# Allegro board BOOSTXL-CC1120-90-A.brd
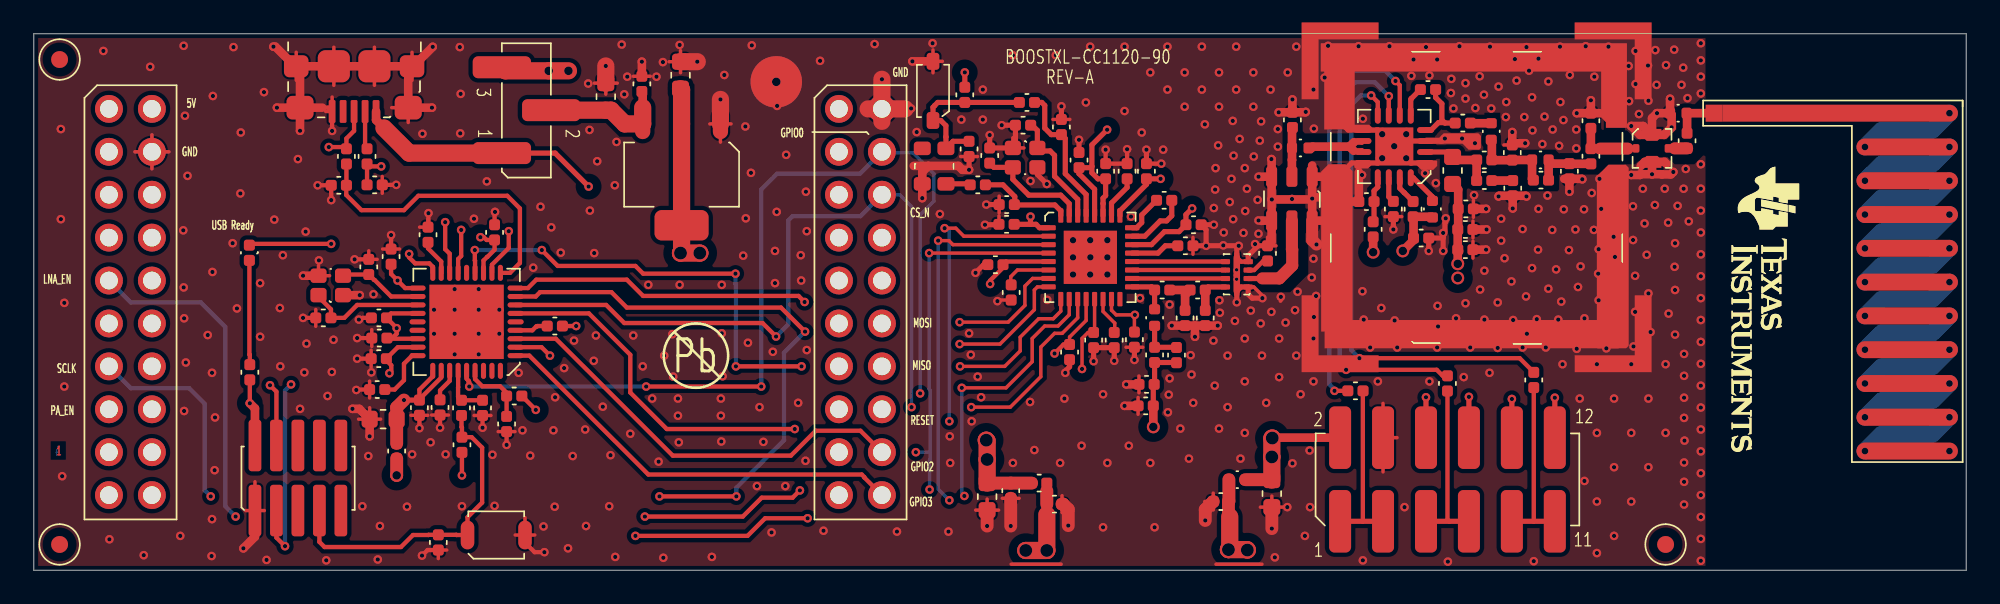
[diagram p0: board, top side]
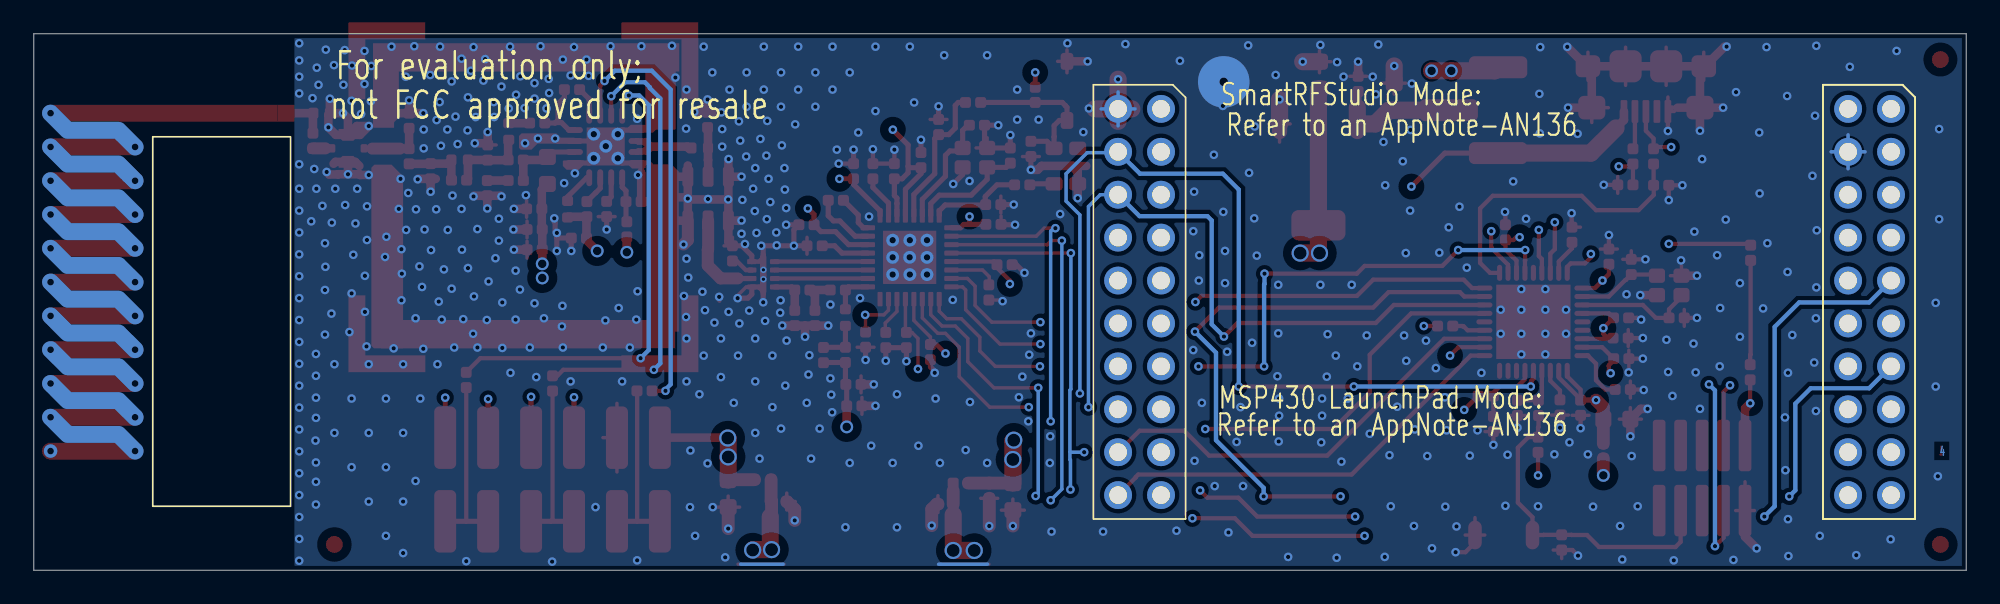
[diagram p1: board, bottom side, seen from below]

Outline 114.3 x 31.75 mm; copper layers: TOP, LAYER2, LAYER3, BOTTOM. Coordinates in mm from the lower left corner of the outline.
Outline path: 0,31.75 114.3,31.75 114.3,0 0,0 0,31.75

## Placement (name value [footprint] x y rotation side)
A1  Antenna PCB 868/915MHz  [ANTENNA868_915MHZ_A2N]  99.39 27.05 270 top
C1  100nF  [CAPC1005X60N]  59.92 3.91 0 top
C2  DNP  [CAPC1005X60N]  57.78 5.16 270 top
C3  2.2uF  [CAPC1608X90N]  56.39 5.16 270 top
C4  47nF  [CAPC1005X60N]  61.26 13.36 270 top
C5  47nF  [CAPC1005X60N]  57.33 18.08 180 top
C6  220nF  [CAPC1005X60N]  57.81 16.89 270 top
C7  47nF  [CAPC1005X60N]  57.99 20.47 180 top
C8  47nF  [CAPC1005X60N]  62.69 14.07 270 top
C9  47nF  [CAPC1005X60N]  65.1 14.1 270 top
C10  33pF  [CAPC1005X60N]  67.59 13.18 270 top
C11  10nF  [CAPC1005X60N]  66.22 9.73 180 top
C12  100pF  [CAPC1005X60N]  66.27 11 180 top
C13  15pF  [CAPC1005X60N]  66.29 16.59 0 top
C14  10nF  [CAPC1005X60N]  67.67 19.2 0 top
C15  47nF  [CAPC1005X60N]  65.81 23.16 90 top
C16  1.8nF  [CAPC1005X60N]  67.31 21.89 180 top
C17  47nF  [CAPC1005X60N]  61.82 23.83 90 top
C18  47nF  [CAPC1005X60N]  68.15 20.45 0 top
C19  47nF  [CAPC1005X60N]  63.4 23.16 90 top
C20  47nF  [CAPC1005X60N]  64.67 23.16 90 top
C21  47nF  [CAPC1005X60N]  60.78 25.78 90 top
C22  0  [CAPC1005X60N]  58.06 26.34 0 top
C23  DNP  [CAPC1005X60N]  56.54 24.99 270 top
C24  22pF  [CAPC1005X60N]  56.29 22.81 180 top
C25  100nF  [CAPC1005X60N]  55.32 24.49 90 top
C26  0.8pF  [CAPC1005X60N]  74.45 27.1 270 top
C27  220pF  [CAPC1005X60N]  70.66 4.06 180 top
C28  10uF  [CAPC1608X100N]  73.23 5.33 270 top
C29  15pF  [CAPC1005X60N]  79.27 21.82 180 top
C30  27pF  [CAPC1005X60N]  81.61 19.66 0 top
C31  47pF  [CAPC1005X60N]  84.25 21.39 0 top
C32  1nF  [CAPC1005X60N]  84.23 20.17 0 top
C33  1uF  [CAPC1005X60N]  84.23 18.97 0 top
C34  12pF  [CAPC1005X60N]  82.02 28.45 0 top
C35  47pF  [CAPC1005X60N]  85.34 24.28 0 top
C36  12pF  [CAPC1005X60N]  84.07 26.47 0 top
C37  3.3pF  [CAPC1005X60N]  87.45 25.17 270 top
C38  7.5pF  [CAPC1005X60N]  90.83 23.16 90 top
C39  DNP  [CAPC1005X60N]  92.1 27.05 270 top
C40  1pF  [CAPC1005X60N]  97.79 24.97 90 top
C41  100nF  [CAPC1005X60N]  27.25 20.45 270 top
C42  2.2uF  [CAPC1608X90N]  21.46 8.94 180 top
C43  220pF  [CAPC1005X60N]  21.13 18.11 90 top
C44  1uF  [CAPC1005X60N]  24.03 10.08 270 top
C45  100nF  [CAPC1005X60N]  19.96 14.94 0 top
C46  100nF  [CAPC1005X60N]  19.99 13.74 0 top
C47  220pF  [CAPC1005X60N]  20.85 12.52 180 top
C48  100nF  [CAPC1005X60N]  22.81 9.17 90 top
C49  47pF  [CAPC1005X60N]  18.49 22.78 180 top
C50  47pF  [CAPC1005X60N]  19.71 22.81 0 top
C51  1nF  [CAPC1005X60N]  26.54 10.06 270 top
C52  33pF  [CAPC1005X60N]  17.58 14.94 180 top
C53  33pF  [CAPC1005X60N]  19.81 17.5 90 top
C56  100nF  [CAPC1005X60N]  35.97 29.24 270 top
C57  10uF  [CAPC1608X100N]  33.83 27.23 90 top
C58  10uF  [CAPC1608X100N]  38.25 28.5 90 top
C59  DNP  [CAPC1005X60N]  87.48 23.06 270 top
C60  DNP  [CAPC1005X60N]  88.7 23.09 0 top
CR1  SML-LX0402SUGC  [LEDC1005X70N]  12.75 18.34 90 top
CR2  1.8V  [SOD3716X135AN]  53.19 26.62 90 top
FIDU1  FIDU_1MM  [FID100X115]  96.52 1.52 0 top
FIDU2  FIDU_1MM  [FID100X115]  1.52 1.52 0 top
FIDU3  FIDU_1MM  [FID100X115]  1.52 30.23 0 top
FL1  LFD21868MMF1D386  [FIL_LFD21868MMF1D386N]  71.83 16.76 90 top
FL2  B39921B3588U410  [FIL_DCC6CN]  75.62 23.29 180 top
J3  1551372-1  [TE_1551372-1_A2N]  94.77 24.97 270 top
J4  1981568-1  [TYCO_19815681N]  20.24 27.15 90 top
L1  BLM15HG102SN1  [INDC1005X60N]  59.92 5.16 180 top
L2  8.2nH  [IND_LQW15AN]  66.29 15.44 270 top
L3  10nH  [IND_LQW15AN]  74.42 24.99 0 top
L4  10nH  [IND_LQW15AN]  70.69 5.36 0 top
L5  1.5nH  [INDC1005X60N]  79.22 20.62 270 top
L6  15nH  [IND_LQW15AN]  82.73 20.88 90 top
L7  22nH  [INDC1608X100N]  83.92 22.86 90 top
L8  7.5nH  [IND_LQW15AN]  86.21 25.48 90 top
L9  2.9nH  [IND_LQW15AN]  88.62 24.28 0 top
L10  9.1nH  [INDC1005X60N]  92.1 24.05 90 top
L11  12nH  [IND_LQW15AN]  97.76 27.05 180 top
L12  BLM15HG102SN1  [INDC1005X60N]  21.46 6.6 90 top
L13  DNP  [INDC1005X60N]  85.34 23.06 0 top
NOREF  -  [#2]  0 0 90 top
NOREF#2  -  [#2]  32.72 0.81 0 top
NOREF#3  -  [#2]  12.29 23.98 0 top
NOREF#4  -  [#2]  -8.36 -41.35 0 top
NOREF#5  -  [#2]  39.17 12.7 0 top
NOREF#6  -  [#2]  0 0 0 top
P1  FTSH-105-01-L-DV-K  [SAMTEC_FTSH-105-01-L-DV-K-10CN]  13.08 3.53 0 top
P2  SSW-110-23-F-D  [SAMTEC_TSW11008SDB]  4.45 27.3 270 top
P3  SSW-110-23-F-D  [SAMTEC_TSW11008SDB]  47.62 27.3 270 top
P6  TSM-106-01-L-DV-P  [SAMTEC_TSM10601LDVPN]  77.27 2.9 0 top
P7  TSM-103-01-L-SV-P  [SAMTEC_TSM10301LSVPN]  27.69 24.69 0 top
R1  56k  [RESC1005X40N]  63.91 14.07 270 top
R3  10  [RESC1005X40N]  66.29 12.29 90 top
R4  DNP  [RESC1005X40N]  57.1 21.64 0 top
R5  470  [RESC1005X40N]  55.07 27.69 90 top
R7  0  [RESC1005X40N]  69.29 16.59 180 top
R8  DNP  [RESC1005X40N]  68.1 14.48 90 top
R9  DNP  [RESC1005X40N]  69.29 14.48 90 top
R10  DNP  [RESC1005X40N]  72.97 19.2 270 top
R11  3.3k  [RESC1005X40N]  80.42 20.93 90 top
R12  47  [RESC1005X40N]  81.58 21.82 270 top
R14  33  [RESC1005X40N]  18.49 24.94 270 top
R15  33  [RESC1005X40N]  19.71 24.94 270 top
R16  1.5k  [RESC1005X40N]  31.27 14.45 180 top
R17  2.7k  [RESC1005X40N]  25.3 10.06 270 top
R18  56k  [RESC1005X40N]  19.86 10.69 0 top
R19  1k  [RESC1005X40N]  12.78 12.17 270 top
R20  1k  [RESC1005X40N]  23.32 19.41 90 top
R21  10k  [RESC1005X40N]  27.97 10.31 0 top
R22  18k  [RESC1005X40N]  27.97 8.2 90 top
R23  10k  [RESC1005X40N]  77.72 10.62 0 top
R24  10k  [RESC1005X40N]  83.62 11.51 270 top
R25  10k  [RESC1005X40N]  88.72 11.71 270 top
R26  4.7k  [RESC1005X40N]  25.32 7.87 270 top
R27  DNP  [RESC1005X40N]  23.93 1.19 90 top
R28  DNP  [RESC1005X40N]  58.29 27.69 0 top
SC1  BMIS-202-F  [MECH_BMIS202FN]  77.27 14 0 top
SW1  B3U-1000PM  [SW_B3U-1000PN]  25.65 2.08 0 top
U1  CC112x/CC120xRHB  [QFNFC50P500X500X100-33BN]  60.02 20.27 270 top
U2  CC1190  [QFNFC65P400X400X100-17AN]  82.32 24.1 90 top
U3  TG-5006CG  [OSCCC200X250X90-4BN]  52.55 24.97 270 top
U4  CC2511F16  [QFNWB50P600X600X90-37N]  28.5 12.7 90 top
U5  TLV1117LV33DCY  [SOT230P700X180-4AN]  40.61 26.42 180 top
UNK#REFDES  -  [unnamed]  104.42 22.89 270 top
Y1  DNP  [XTAL_FA128N]  59.36 24.99 180 top
Y2  48MHz  [XTAL_FA128N]  16.84 16.28 0 top

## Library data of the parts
A1 = ANTENNA: User Part Number: #PN
C1 C2 C4-C9 C11-C27 C29-C41 C43-C51 C56 C59 C60 = CAPACITOR: User Part Number: #PN; alternate symbols: (CAPC1005X60L,CAPC1005X60M)
C3 C42 = CAPACITOR: alternate symbols: (CAPC1608X90L,CAPC1608X90M)
C10 C52 C53 = CAPACITOR: User Part Number: #PN; alternate symbols: (CAPC1005X60M,CAPC1005X60L)
C28 C57 C58 = CAPACITOR: alternate symbols: (CAPC1608X100L,CAPC1608X100M)
CR1 = LED_AC: alternate symbols: (LEDC1005X70L,LEDC1005X70M)
CR2 = DIODE_ZENER: alternate symbols: (SOD3716X135AL,SOD3716X135AM)
FIDU1-FIDU3 = FIDMARK
FL1 = FILTER_LFD21868MMF1D386: alternate symbols: (FIL_LFD21868MMF1D386L,FIL_LFD21868MMF1D386M)
FL2 = FILTER_SAW_RF_B3588: alternate symbols: (FIL_DCC6CL,FIL_DCC6CM)
J3 = CONN_COAX_1551372-1: User Part Number: #PN; alternate symbols: (TE_1551372-1_A2L,TE_1551372-1_A2M)
J4 = CONN_USB_MICRO_5+6_S: alternate symbols: (TYCO_19815681L,TYCO_19815681M)
L1 L5 L10 L12 L13 = INDUCTOR: alternate symbols: (INDC1005X60L,INDC1005X60M)
L2-L4 L6 L8 L9 L11 = INDUCTOR: alternate symbols: (IND_LQW15AM,IND_LQW15AL)
L7 = INDUCTOR: alternate symbols: (INDC1608X100L,INDC1608X100M)
P1 = CONN_HEADER_2X5: alternate symbols: (SAMTEC_FTSH-105-01-L-DV-K-10CL,SAMTEC_FTSH-105-01-L-DV-K-10CM)
P2 P3 = CONN_HEADER_2X10_P_S_V1: alternate symbols: (SAMTEC_TSW11008SDC,SAMTEC_TSW11008SDA)
P6 = CONN_HEADER_2X6_P_S: User Part Number: #PN; alternate symbols: (SAMTEC_TSM10601LDVPL,SAMTEC_TSM10601LDVPM)
P7 = CONN_HEADER_3_P_S: User Part Number: #PN; alternate symbols: (SAMTEC_TSM10301LSVPL,SAMTEC_TSM10301LSVPM)
R1 R3-R5 R7-R12 R14-R28 = RESISTOR: alternate symbols: (RESC1005X40L,RESC1005X40M)
SC1 = SHIELD_COVER_BMIS-202: User Part Number: #PN
SW1 = SWITCH_2PIN: alternate symbols: (SW_B3U-1000PL,SW_B3U-1000PM)
U1 = IC_RF_CC1120_QFN32: alternate symbols: (QFNFC50P500X500X100-33BL,QFNFC50P500X500X100-33BM)
U2 = IC_RF_CC1190_QFN16: alternate symbols: (QFNFC65P400X400X100-17AL,QFNFC65P400X400X100-17AM)
U3 = XTAL_TG-5021CG: alternate symbols: (OSCCC200X250X90-4BL,OSCCC200X250X90-4BM)
U4 = IC_RF_CC2511F_QFN36: alternate symbols: (QFNWB50P600X600X90-37L,QFNWB50P600X600X90-37M)
U5 = IC_PM_LM317M_SOT223-4: alternate symbols: (SOT230P700X180-4AL,SOT230P700X180-4AM)
Y1 Y2 = XTAL_4: alternate symbols: (XTAL_FA128L,XTAL_FA128M)

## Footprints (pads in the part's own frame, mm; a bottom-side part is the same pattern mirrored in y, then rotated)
ANTENNA868_915MHZ_A2N
  rect 1x1 smd: 1(0,0)
CAPC1005X60N
  custom 0.16x0.16 smd: 1(0,0) 2(0.9,0)
CAPC1608X90N
  custom 0.237x0.237 smd: 1(0,0) 2(1.6,0)
CAPC1608X100N
  custom 0.237x0.237 smd: 1(0,0) 2(1.6,0)
FID100X115
  round 1 smd: 1(0,0)
FIL_DCC6CN
  custom 0.163x0.163 smd: 1(0,0) 2(1.2,0) 3(2.4,0) 4(2.4,2.6) 5(1.2,2.6) 6(0,2.6)
FIL_LFD21868MMF1D386N
  custom 0.075x0.075 smd: 1(0,0) 2(0.5,0) 3(1,0) 4(1.5,0) 5(1.75,0.675) 6(1.5,1.35) 7(1,1.35) 8(0.5,1.35) 9(0,1.35) 10(-0.25,0.675)
IND_LQW15AN
  custom 0.15x0.15 smd: 1(0,0) 2(0.98,0)
INDC1005X60N
  custom 0.16x0.16 smd: 1(0,0) 2(0.9,0)
INDC1608X100N
  custom 0.237x0.237 smd: 1(0,0) 2(1.6,0)
LEDC1005X70N
  custom 0.163x0.163 smd: 1(0,0) 2(0.9,0)
MECH_BMIS202FN
  custom 1.138x1.138 smd: 1(0,0) 3(16.15,0) 5(16.15,16.15) 7(0,16.15)
  custom 0.25x0.25 smd: 2(8.075,-0.075) 4(16.225,8.075) 6(8.075,16.225) 8(-0.075,8.075)
OSCCC200X250X90-4BN
  custom 0.199x0.199 smd: 1(0,0) 2(2.1,0) 3(2.1,1.4) 4(0,1.4)
QFNFC50P500X500X100-33BN
  custom 0.075x0.075 smd: 1(0,0) 2(0.5,0) 3(1,0) 4(1.5,0) 5(2,0) 6(2.5,0) 7(3,0) 8(3.5,0) 9(4.225,0.725) 10(4.225,1.225) 11(4.225,1.725) 12(4.225,2.225) 13(4.225,2.725) 14(4.225,3.225) 15(4.225,3.725) 16(4.225,4.225) 17(3.5,4.95) 18(3,4.95) 19(2.5,4.95) 20(2,4.95) 21(1.5,4.95) 22(1,4.95) 23(0.5,4.95) 24(0,4.95) 25(-0.725,4.225) 26(-0.725,3.725) 27(-0.725,3.225) 28(-0.725,2.725) 29(-0.725,2.225) 30(-0.725,1.725) 31(-0.725,1.225) 32(-0.725,0.725)
  rect 3.15x3.15 smd: 33(1.75,2.475)
QFNFC65P400X400X100-17AN
  oval 0.35x1 smd: 1(0,0) 2(0.65,0) 3(1.3,0) 4(1.95,0) 9(1.95,3.7) 10(1.3,3.7) 11(0.65,3.7) 12(0,3.7)
  oval 1x0.35 smd: 5(2.825,0.875) 6(2.825,1.525) 7(2.825,2.175) 8(2.825,2.825) 13(-0.875,2.825) 14(-0.875,2.175) 15(-0.875,1.525) 16(-0.875,0.875)
  rect 2.25x2.25 smd: 17(0.975,1.85)
QFNWB50P600X600X90-37N
  oval 0.3x0.95 smd: 1(0,0) 2(0.5,0) 3(1,0) 4(1.5,0) 5(2,0) 6(2.5,0) 7(3,0) 8(3.5,0) 9(4,0) 19(4,5.8) 20(3.5,5.8) 21(3,5.8) 22(2.5,5.8) 23(2,5.8) 24(1.5,5.8) 25(1,5.8) 26(0.5,5.8) 27(0,5.8)
  oval 0.95x0.3 smd: 10(4.9,0.9) 11(4.9,1.4) 12(4.9,1.9) 13(4.9,2.4) 14(4.9,2.9) 15(4.9,3.4) 16(4.9,3.9) 17(4.9,4.4) 18(4.9,4.9) 28(-0.9,4.9) 29(-0.9,4.4) 30(-0.9,3.9) 31(-0.9,3.4) 32(-0.9,2.9) 33(-0.9,2.4) 34(-0.9,1.9) 35(-0.9,1.4) 36(-0.9,0.9)
  rect 4.4x4.4 smd: 37(2,2.9)
RESC1005X40N
  custom 0.16x0.16 smd: 1(0,0) 2(0.9,0)
SAMTEC_FTSH-105-01-L-DV-K-10CN
  custom 0.187x0.187 smd: 1(0,0) 2(0,3.85) 3(1.27,0) 4(1.27,3.85) 5(2.54,0) 6(2.54,3.85) 7(3.81,0) 8(3.81,3.85) 9(5.08,0) 10(5.08,3.85)
SAMTEC_TSM10301LSVPN
  custom 0.325x0.325 smd: 1(0,0) 2(2.92,2.54) 3(0,5.08)
SAMTEC_TSM10601LDVPN
  custom 0.325x0.325 smd: 1(0,0) 2(0,4.95) 3(2.54,0) 4(2.54,4.95) 5(5.08,0) 6(5.08,4.95) 7(7.62,0) 8(7.62,4.95) 9(10.16,0) 10(10.16,4.95) 11(12.7,0) 12(12.7,4.95)
SAMTEC_TSW11008SDB
  round 1.65 hole 1.05: 1(0,0) 2(0,2.54) 3(2.54,0) 4(2.54,2.54) 5(5.08,0) 6(5.08,2.54) 7(7.62,0) 8(7.62,2.54) 9(10.16,0) 10(10.16,2.54) 11(12.7,0) 12(12.7,2.54) 13(15.24,0) 14(15.24,2.54) 15(17.78,0) 16(17.78,2.54) 17(20.32,0) 18(20.32,2.54) 19(22.86,0) 20(22.86,2.54)
SOD3716X135AN
  custom 0.187x0.187 smd: 1(0,0) 2(3.5,0)
SOT230P700X180-4AN
  oval 0.9x1.8 smd: 1(0,0) 2(2.3,0) 3(4.6,0)
  custom 0.45x0.45 smd: 4(2.3,6)
SW_B3U-1000PN
  oval 0.8x1.7 smd: 1(0,0) 2(3.4,0)
TE_1551372-1_A2N
  custom 0.1x0.1 smd: 1(0,0) 2(0,1.9)
  custom 0.175x0.175 smd: M1(-0.8,0.95) M2(0.8,0.95)
TYCO_19815681N
  custom 0.1x0.1 smd: 1(0,0) 2(0,0.65) 3(0,1.3) 4(0,1.95) 5(0,2.6)
  custom 0.35x0.35 smd: 6(0.225,-1.903) 7(0.225,4.497)
  custom 0.325x0.325 smd: 8(2.675,-2.128) 9(2.675,4.722)
  custom 0.475x0.475 smd: 10(2.675,0.097) 11(2.675,2.497)
unnamed
  round 0.001 smd: 1(1.65,-3.9)
XTAL_FA128N
  custom 0.212x0.212 smd: 1(0,0) 2(1.45,0) 3(1.45,1.15) 4(0,1.15)

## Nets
3V3: C1.1 C27.1 C58.1 L1.1 L4.1 L12.1 P1.2 R19.2 R26.2 U5.2(OUT#2) U5.4(OUT#4)
GND: C1.2 C2.2 C3.2 C4.2 C5.2 C6.2 C7.2 C8.2 C9.2 C11.2 C12.2 C14.2 C15.2 C17.2 C18.2 C19.2 C20.2 C21.2 C22.1 C23.1 C25.1 C26.1 C27.2 C28.2 C29.2 C30.2 C31.2 C32.2 C33.2 C37.1 C38.1 C39.1 C41.1 C42.2 C43.2 C44.2 C45.1 C46.1 C47.2 C48.1 C49.2 C50.2 C51.2 C52.2 C53.2 C56.1 C57.2 C58.2 C59.2 CR2.2(ANODE) FL1.1(GND#1) FL1.4(GND#4) FL1.5(GND#5) FL1.10(GND#10) FL2.1(GND#1) FL2.3(GND#3) FL2.4(GND#4) FL2.6(GND#6) J3.M1 J3.M2 J4.5(GND#5) J4.6(GND#6) J4.7(GND#7) J4.8(GND#8) J4.9(GND#9) J4.10(GND#10) J4.11(GND#11) L11.2 P1.1 P2.4 P3.2 P6.4 R1.2 R4.1 R8.1 R9.1 R10.1 R11.1 R18.1 R20.2 R22.1 R27.1 SC1.1(GND#1) SC1.2(GND#2) SC1.3(GND#3) SC1.4(GND#4) SC1.5(GND#5) SC1.6(GND#6) SC1.7(GND#7) SC1.8(GND#8) SW1.2 U1.33(EGP) U2.1(GND#1) U2.3(GND#3) U2.9(GND#9) U2.12(GND#12) U2.17(GND#17) U3.2(GND) U4.37(AGND) U5.1(ADJ) Y1.2 Y1.4 Y2.2 Y2.4
VDD_CC112X: C2.1 C3.1 C4.1 C5.1 C7.1 C8.1 C9.1 C10.2 C11.1 C12.1 C15.1 C17.1 C18.1 C19.1 L1.2 R3.1 R5.2 U1.1(VDD_GUARD) U1.5(DVDD#5) U1.12(DVDD#12) U1.13(AVDD_IF) U1.15(AVDD_RF) U1.22(AVDD_SYNTH1) U1.25(AVDD_PFD_CHP) U1.27(AVDD_SYNTH2) U1.28(AVDD_XOSC)
VDD_CC1190: C28.1 C30.1 C31.1 C32.1 C33.1 L4.2 L5.2 L6.1 L7.1 P6.2 R12.2
VDD_CC2511: C41.2 C42.1 C43.1 C45.2 C46.2 C47.1 C48.2 L12.2 U4.2(DVDD#2) U4.12(DVDD#12) U4.19(AVDD#19) U4.22(AVDD#22) U4.25(AVDD#25) U4.26(AVDD#26) U4.28(GUARD) U4.29(AVDD_DREG)
CC112X_RF: FL1.2(ANT) FL2.5(OUT)
COM_5V: C56.2 C57.1 P7.2 U5.3(IN)
DBG_DC: P1.3 U4.16(P2_2)
DBG_DD: P1.4 U4.15(P2_1)
DCPL_XOSC: C21.1 R28.2 U1.29(DCPL_XOSC)
HGM: R23.1 U2.6(HGM)
LNA_EN: R24.1 U2.7(LNA_EN)
LNA_EN_LP: P2.9 P6.6
LP_5V: P2.2 P7.3
PA_EN: R25.1 U2.8(PA_EN)
PA_EN_LP: P2.15 P6.10
RF_GPIO0: P3.4 P6.12 U1.10(GPIO0) U4.32(P1_7)
RF_GPIO2: P3.18 P6.8 U1.4(GPIO2) U4.3(P1_1)
RF_GPIO3: P3.20 U1.3(GPIO3) U4.1(P1_2)
RF_RESET_N: P3.16 U1.2(RESET_N) U4.6(P0_1)
RF_SPI_CS_N: P3.6 U1.11(CS_N) U4.7(P0_2)
RF_SPI_MISO(GPIO1): P3.14 U1.9(SO(GPIO1)) U4.13(P0_5)
RF_SPI_MOSI: P3.12 U1.7(SI) U4.9(P0_4)
RF_SPI_SCLK: P2.13 U1.8(SCLK) U4.8(P0_3)
USB_5V: J4.1(VBUS) P7.1 R21.2
USB_ENABLE: R21.1 R22.2 U4.33(P1_6)
USB_PULLUP: R16.2 U4.4(P1_0)
USB_RESET: P1.7 R17.2 R26.1 R27.2 SW1.1
N333157: C13.1 L2.1 U1.17(PA)
N333170: C10.1 L2.2 R3.2
N333547: C13.2 R7.2 R8.2
N333561: FL1.9(TXPA) R7.1 R9.2
N333614: FL1.8(TRX) U1.18(TRX_SW)
N333626: FL1.6(RX1LNA_N) U1.20(LNA_N)
N333651: FL1.7(RX2LNA_P) U1.19(LNA_P)
N334768: R1.1 U1.14(RBIAS)
N334780: C16.2 U1.24(LPF1)
N334837: C16.1 U1.23(LPF0)
N335035: C25.2 CR2.1(CATHODE) R5.1 R28.1 U3.4(VCC)
N335193: C22.2 U1.30(XOSC_Q1) Y1.1
N335253: C23.2 U1.31(XOSC_X2) Y1.3
N337409: FL1.3(NC) R10.2
N339345: C20.1 U1.26(DCPL_PFD_CHP)
N339363: C14.1 U1.21(DCPL_VCO)
N339381: C6.1 U1.6(DCPL)
N340434: C24.1 R4.2 U1.32(EXT_OSC)
N340490: C24.2 U3.3(OUT)
N342853: L3.2 U2.10(LNA_OUT) U2.11(PA_IN)
N342874: C26.2 FL2.2(IN) L3.1
N343088: R11.2 U2.14(BIAS)
N343666: R12.1 U2.15(VDD_PA2)
N343673: L6.2 U2.16(VDD_PA1)
N343813: C29.1 L5.1 U2.13(VDD_LNA)
N344199: C35.1 L7.2 L13.1 U2.2(PA_OUT)
N344697: C34.2 C36.1 U2.4(TR_SW)
N344701: C34.1 U2.5(LNA_IN)
N344947: C35.2 C37.2 C60.1 L8.1 L9.1
N345002: C38.2 C60.2 L9.2 L10.1
N345235: C39.2 J3.1(IN) L10.2
N348306: A1.1(FEED/GND_1) C40.2 L11.1
N349314: C44.1 U4.30(DCOUPL)
N350057: C49.1 R14.2 U4.10(DP)
N350061: J4.3(D+) R14.1 R16.1
N350083: C50.1 R15.2 U4.11(DM)
N350090: J4.2(D-) R15.1
N350965: C51.1 R17.1 U4.31(NRESET)
N351165: R18.2 U4.27(RBIAS)
N351342: C52.1 U4.21(XOSC_Q1) Y2.1
N351349: C53.1 U4.20(XOSC_Q2) Y2.3
N352690: CR1.2(C) U4.18(P2_4/XOSC32_Q2)
N352702: CR1.1(A) R19.1
N352706: R20.1 U4.17(P2_3/XOSC32_Q1)
N367241: P6.9 P6.11 R25.2
N367275: P6.5 P6.7 R24.2
N367294: P6.1 P6.3 R23.2
N398938: C36.2 L8.2
N399362: C59.1 L13.2
N401261: C40.1 J3.2(OUT)

Pads without a net: FIDU1 1; FIDU2 1; FIDU3 1; J4 4; P1 5 6 8 9 10; P2 1 3 5 6 7 8 10 11 12 14 16 17 18 19 20; P3 1 3 5 7 8 9 10 11 13 15 17 19; U1 16; U3 1; U4 5 14 23 24 34 35 36; UNK#REFDES 1

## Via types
v1: diameter 0.8, hole 0.4, TOP to BOTTOM, 21 vias
v2: diameter 0.508, hole 0.254, TOP to BOTTOM, 672 vias
v3: diameter 1.016, hole 0.762, TOP to BOTTOM, 10 vias
v4: diameter 0.762, hole 0.508, TOP to BOTTOM, 8 vias
v5: diameter 0.762, hole 0.381, TOP to BOTTOM, 14 vias
v6: diameter 0.381, hole 0.203, TOP to BOTTOM, 2 vias
v7: diameter 3.048, hole 0.508, TOP to BOTTOM, 1 via

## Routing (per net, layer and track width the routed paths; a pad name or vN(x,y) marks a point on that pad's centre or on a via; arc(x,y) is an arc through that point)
3V3: length 109.5
  TOP w0.254: R19.2 v2(12.78,9.88) ; R26.2 v2(25.32,5.61)
  TOP w0.508: 59.92,3.28 C1.1 ; P1.2 13.08,9.58 v2(12.78,9.88) ; 59.92,4.7 L1.1
  TOP w0.762: v3(70.66,1.22) 70.64,1.19 ; L4.1 70.69,4.09 C27.1 70.66,3.24 70.74,3.16 ; L12.1 v4(21.46,5.61) ; C1.1 59.92,4.7
  TOP w1.016: v3(58.67,1.17) v3(59.92,1.17) 59.92,3.28 ; C58.1 38.31,28.44 U5.2 U5.4 38.31,18.83 v3(38.25,18.77) v3(39.4,18.77) ; v3(71.78,1.19) 71.75,1.22 v3(70.66,1.22) 70.74,1.3 70.74,3.16
  LAYER3 w0.254: 25.3,5.61 25.27,5.59
  LAYER3 w0.508: v4(21.46,5.61) 21.49,5.59
  LAYER3 w1.016: v2(25.32,5.61) 23.72,5.61 23.7,5.59 13.56,5.59 12.78,6.38 v2(12.78,9.88) ; v3(38.25,18.77) v3(39.4,18.77) 39.4,5.59 ; 25.27,5.59 39.4,5.59 ; 39.4,5.59 39.4,3.45 41.66,1.19 59.89,1.19 v3(59.92,1.17) 71.83,1.17 71.78,1.22 v3(70.66,1.22)
GND: length 296.1
  TOP w0.203: 57.1,21.14 R4.1 57.1,22.14 ; 22.15,26.5 J4.6 21.17,27.38 ; 79.81,5.82 P6.4 ; P6.4 79.81,9.87 ; P6.4 80.64,7.85 ; 22.82,20.31 R20.2 23.32,20.81 ; 19.95,13.02 C47.2 19.95,12.02 ; 65.37,11.5 C12.2 65.37,10.5 ; 26.04,9.16 C51.2 27.04,9.16 ; 69.26,4.06 C27.2 ; C27.2 69.76,3.57 ; C27.2 69.76,4.56 ; C28.2 73.91,3.73 ; C28.2 73.23,4.39 ; C28.2 72.55,3.73 ; 55.82,24.49 C25.1 54.82,24.49 ; 72.97,19.71 R10.1 73.47,19.2 ; 36.46,29.24 C56.1 35.47,29.24 ; SW1.2 29.63,2.08 ; SW1.2 28.48,2.08 ; SW1.2 29.05,3.11 ; 19.81,18.9 C53.2 20.31,18.4 ; v2(73.76,16.18) 73.76,15.95 73.74,15.93 ; C3.2 56.39,4.21 ; C3.2 55.71,3.56 ; C3.2 57.07,3.56 ; 85.13,19.47 C33.2 85.13,18.48 ; 68.57,18.7 C14.2 68.57,19.7 ; 39.99,26.42 U5.1 ; U5.1 41.24,26.42 ; U5.1 40.61,25.34 ; P2.4 6.99,25.77 ; P2.4 6.99,23.76 ; P2.4 5.98,24.77 ; P2.4 7.99,24.77 ; 22.31,9.17 C48.1 23.31,9.17 ; C58.2 38.25,30.75 ; C58.2 38.25,29.45 ; C58.2 37.57,30.1 ; 60.82,4.41 C1.2 60.82,3.41 ; C42.2 20.52,8.94 ; C42.2 19.86,9.62 ; C42.2 19.21,8.94 ; 20.15,28.7 J4.10 20.15,30.96 ; 24.43,1.19 R27.1 23.93,0.69 ; 72.64,16.28 72.16,16.76 FL1.1 ; 49.16,27.3 49.35,27.3 ; 17.75,30.96 J4.11 17.75,28.7 ; 57.29,4.26 C2.2 58.28,4.26 ; 23.53,9.18 C44.2 24.53,9.18 ; 57.81,0.36 60.76,0.36 ; 16.84,18.03 Y2.4 17.49,17.43 ; 17.27,27.15 J4.5 17.64,28.01 ; 61.28,26.68 C21.2 60.28,26.68 ; C6.2 57.06,15.99 v2(57,15.93) ; 15.52,30.66 J4.9 15.52,29 ; 20.63,19.01 C43.2 21.63,19.01 ; 20.61,23.31 C50.2 20.61,22.31 ; 87.95,25.17 C37.1 86.95,25.17 ; 57.91,25.6 Y1.2 58.56,24.99 ; CR2.2 53.19,30.8 ; CR2.2 53.74,30.12 ; CR2.2 53.19,29.44 ; 22.37,29 J4.8 22.37,30.66 ; 57.09,20.97 C7.2 56.58,20.47 ; 69.93,0.36 72.64,0.36 ; P1.1 13.63,3.53 ; P1.1 13.08,5.23 ; P1.1 12.53,3.53 ; 19.99,14.24 C46.1 19.99,13.24 ; 65.6,13.2 C9.2 64.6,13.2 ; 85.13,19.67 C32.2 85.13,20.67 ; 19.86,11.19 R18.1 19.86,10.2 ; 33.83,28.18 C57.2 ; C57.2 33.15,28.83 ; C57.2 34.51,28.83 ; 65.32,9.23 C11.2 65.32,10.23 ; 75.62,24.07 75.62,23.95 ; 50.16,26.3 50.16,26.57 ; 85.15,20.89 C31.2 85.15,21.89 ; 16.68,15.43 C52.2 16.68,14.44 ; 27.47,8.2 R22.1 28.46,8.2 ; 79.92,20.93 R11.1 80.91,20.93
  TOP w0.254: C15.2 v2(66.69,24.06) ; 71.16,17.67 71.15,17.68 v6(71.15,17.78) ; C46.1 v2(19.13,13.74) ; C44.2 v2(24.03,8.43) ; v2(30.2,1.07) 29.62,1.07 29.05,1.63 SW1.2 ; v2(64.67,24.92) C20.2 C19.2 v2(63.4,24.89) ; v6(71.15,17.22) 71.15,17.44 71.16,17.45 ; FL1.5 71.41,18.26 FL1.4 ; 17.06,27.38 17.42,27.38 J4.5 v2(17.64,26) ; C48.1 v2(22.81,8.41) ; C47.2 v2(19.13,12.52) ; 23.34,20.15 v2(23.34,21.13) ; v2(16.79,22.78) C49.2 v2(17.59,21.91) ; C45.1 19.46,14.94 19.35,14.83 v2(19.23,14.83) ; v2(19.08,10.67) 19.1,10.69 R18.1 19.91,10.69 ; C41.1 27.25,21.18 v2(27.28,21.21) ; C51.2 v2(26.54,8.43) ; C53.2 v2(18.97,18.4) ; R22.1 v2(27.97,7.42) ; C43.2 v2(21.13,19.84) ; C52.2 v2(15.93,14.94) ; v2(22.96,0.86) 23.29,1.19 R27.1 ; C50.2 v2(21.44,22.81)
  TOP w0.305: C7.2 57.06,20.45 v2(56.26,20.45) ; v2(69.34,19.2) v2(71.27,19.2) 71.16,19.09 FL1.5 ; v2(69.34,19.2) C14.2 ; v2(69.34,19.2) 69.34,20.15 C18.2 v2(69.8,20.45) ; v2(63.91,12.4) R1.2 C8.2 v2(62.69,12.37) ; v2(82.51,18.9) C30.2 83.34,19.66 83.36,19.68 ; 83.36,19.68 v2(83.36,18.9) ; 83.36,19.68 v2(83.36,19.96) 83.46,20.07 83.46,20.57 83.52,20.62 v2(83.52,20.83) ; U2.12 79.5,24.1 U2.17 ; U2.12 77.95,24.1 77.19,23.34 SC1.8 ; U2.12 78.37,23.86 78.37,23.55 ; C5.2 56.18,18.08 v2(55.7,17.6) ; v2(72.67,16.1) 72.06,16.1 71.83,16.33 FL1.1 71.41,16.76 FL1.10 v2(71.16,15.86) ; C15.2 v2(65.81,24.89) ; U2.1 81.45,24.1 U2.17 ; R4.1 v2(56.34,21.64) ; C25.1 v2(55.32,23.7) ; v2(59.92,22.86) 59.36,23.42 Y1.4 ; C9.2 v2(65.1,12.45) ; U2.17 79.5,26.05 U2.9 77.74,26.05 77.27,26.53 SC1.7 ; U2.17 80.8,25.4 U2.3 83.23,25.4 83.24,25.4 83.31,25.4 v2(83.46,25.55) ; C21.2 v2(60.78,27.46) ; FL1.4 71.83,18.62 72.42,19.2 R10.1 ; C4.2 61.26,12.04 61.01,11.79 v2(61.01,11.68) ; R11.1 v2(80.42,20.17) ; v2(56.54,25.76) C23.1 57.73,24.99 57.91,24.82 58.06,24.97 C22.1 v2(57.25,26.34) ; C17.2 v2(61.82,25.48)
  TOP w0.381: FL1.10 FL1.5
  TOP w0.508: C26.1 75.21,27.1 v2(75.23,27.13) ; C26.1 v2(74.45,27.86) ; C26.1 v2(73.63,27.1) ; v2(14.17,30.99) 14.29,30.99 15.45,29.83 J4.9 ; C39.1 v2(91.26,27.05) ; C39.1 92.61,27.05 ; C39.1 v2(92.1,27.81) ; v2(95.72,23.44) 96.29,23.44 96.3,23.42 96.83,23.42 v2(96.98,23.57) ; v2(95.72,23.44) J3.M2 ; v2(95.72,23.44) 95.04,23.44 95,23.39 v2(94.49,23.39) ; 68.68,14.48 v2(68.68,13.82) ; 68.68,14.48 R9.1 v2(70.03,14.48) ; 68.68,14.48 R8.1 v2(67.31,14.48) ; v2(55.32,23.7) 54.92,23.7 54.69,23.93 52.91,23.93 ; FL2.4 72.63,20.69 72.62,20.68 ; FL2.4 73.22,21.95 ; FL2.4 73.22,19.44 R10.1 ; J3.M1 96.43,25.77 v2(96.88,26.21) 96.88,26.96 L11.2 ; J3.M1 95.72,26.76 v2(96.01,27.05) L11.2 ; J3.M1 95.2,26.29 v2(94.49,26.29) 95.01,25.77 J3.M1 ; Y2.4 v2(15.93,17.43) ; P1.1 13.08,1.98 v2(12.4,1.3) ; v2(87.45,25.93) C37.1 87.55,25.27 v2(88.21,25.27) ; C59.2 v2(87.48,21.41) ; C59.2 86.68,22.16 v2(86.64,22.12) ; C59.2 88.25,22.16 v2(88.29,22.12) ; v2(18.85,9.55) 19.25,9.55 C42.2 v2(19.86,7.92) ; v2(91.59,23.14) 91.57,23.16 C38.1 ; J3.M2 96.46,24.17 96.57,24.06 ; J3.M2 95.29,24.17 95.05,23.93 ; v2(23.55,27.38) J4.6 22.15,29.6 J4.8 ; CR2.2 v2(51.97,30.12) ; J4.9 J4.11 J4.10 J4.8 ; J4.9 15.75,29.6 J4.7 ; Y2.2 v2(19.28,16.28) ; 76.31,23.32 76.29,23.29 FL2.1 ; 73.22,21.95 v2(73.23,21.95) 75.62,21.95 ; 73.22,21.95 FL2.3 ; v2(23.6,30.98) 22.45,29.83 J4.8 ; FL2.1 v2(75.62,22) 75.62,21.95 ; FL2.1 75.62,23.95 ; J4.7 v2(14.38,27.38) ; J4.7 v2(15.75,26.01) ; J4.7 17.06,27.38 ; C33.2 v2(85.9,18.97) ; v2(52.55,22.02) U3.2 52.55,23.57 52.91,23.93 ; C31.2 v2(85.9,21.39) ; v2(73.2,24.33) 73.22,24.32 FL2.3 ; C11.2 v2(64.52,9.73) ; L11.2 v2(96.78,27.9) ; C38.1 v2(90.83,22.4) ; C38.1 90.53,23.16 ; FL2.3 72.54,23.29 ; 75.62,21.95 FL2.6 76.3,20.69 76.31,20.7 ; 75.62,21.95 75.74,22.07 SC1.8 77.44,21.82 C29.2 78.37,23.55 ; 52.91,23.93 52.05,23.93 ; C32.2 v2(85.93,20.17) ; C56.1 v2(35.97,30.1) ; C12.2 v2(64.62,11)
  TOP w0.711: v2(75.87,19.28) 75.62,19.53 FL2.6
  TOP w0.762: v2(61.19,2.64) 61.19,3.61 60.88,3.91 C1.2 ; C28.2 v2(73.23,2.46) ; v2(69.29,2.95) 69.29,3.59 C27.2 ; C2.2 v2(57.78,2.62) ; C3.2 v2(56.39,2.62)
  TOP w1.016: 49.35,27.3 P3.2 ; P3.2 51.54,27.3 ; P3.2 50.16,26.57 ; P3.2 v2(50.16,29.06) ; U5.1 v2(40.61,27.86) ; C58.2 v2(39.24,30.1) ; C57.2 v2(33.83,29.84)
  LAYER2 w0.203: 49.16,27.3 P3.2 ; P3.2 51.17,27.3 ; P3.2 50.16,26.3 ; P3.2 50.16,28.31 ; 5.98,24.77 P2.4 ; P2.4 6.99,25.77 ; P2.4 7.99,24.77 ; P2.4 6.99,23.76 ; 57.78,0.36 60.78,0.36 ; 69.93,0.36 72.62,0.36
  LAYER3 w0.203: P2.4 7.99,24.77 ; P2.4 6.99,23.76 ; P2.4 5.98,24.77 ; P2.4 6.99,25.77 ; 70.03,0.36 72.62,0.36 ; 57.94,0.36 60.66,0.36 ; 50.16,26.3 P3.2 ; P3.2 49.16,27.3 ; P3.2 50.16,28.31 ; P3.2 51.17,27.3
  BOTTOM w0.203: 49.16,27.3 P3.2 ; P3.2 50.16,28.31 ; P3.2 51.17,27.3 ; P3.2 50.16,26.3 ; 5.98,24.77 P2.4 ; P2.4 6.99,25.77 ; P2.4 7.99,24.77 ; P2.4 6.99,23.76 ; 69.98,0.36 72.49,0.36 ; 57.89,0.36 60.78,0.36
  vias: v2(1.6,26.11) v2(1.6,20.78) v2(1.68,5.56) v2(1.8,15.82) v2(1.8,10.87) v2(4.11,30.73) v2(4.47,1.83) v2(6.5,0.89) v2(6.88,29.79) v2(8.66,2.03) v2(8.84,20.12) v2(8.86,31.04) v2(8.94,26.9) v2(8.86,16.74) v2(8.89,14.91) v2(8.89,9.42) v2(8.99,12.29) v2(9.09,23.34) v2(10.29,13.92) v2(10.54,11.68) v2(10.54,3.02) v2(10.52,0.84) v2(10.59,28.07) v2(10.57,17.65) v2(10.72,9.04) v2(10.69,5.92) v2(11.81,30.96) v2(11.76,19.35) v2(12.01,15.49) v2(12.24,25.91) v2(12.22,22.3) v2(13.39,16.99) v2(13.39,13.82) v2(13.61,28.3) v2(13.77,0.61) v2(14.22,20.75) v2(14.55,15.52) v2(14.58,12.06) v2(14.73,18.64) v2(15.62,24.33) v2(15.75,9.55) v2(16,11.71) v2(16.08,20.04) v2(16.13,13.41) v2(16.87,18.34) v2(17.3,0.58) v2(17.37,10.31) v2(17.63,11.73) v2(17.73,13.64) v2(19.43,3.78) v2(19.79,6.76) v2(19.96,11.71) v2(20.09,16.33) v2(20.35,0.64) v2(20.47,2.62) v2(22.07,3.76) v2(22.38,6.86) v2(22.99,25.83) v2(23.47,7.57) v2(23.67,15.42) v2(23.67,14) v2(24.36,6.86) v2(24.89,16.64) v2(24.89,15.42) v2(24.89,14) v2(24.89,12.78) v2(25.2,30.96) v2(25.25,28.19) v2(25.22,25.86) v2(25.32,3.78) v2(26.04,20.8) v2(26.31,16.64) v2(26.31,15.42) v2(26.31,14) v2(26.31,12.78) v2(26.8,23.01) v2(27.13,6.83) v2(27.25,3.81) v2(27.53,15.42) v2(27.53,14) v2(28.68,11.68) v2(28.91,8.28) v2(29.36,6.78) v2(29.54,17.91) v2(29.97,21.51) v2(30.15,2.59) v2(30.61,20.29) v2(30.73,8.28) v2(30.84,10.24) v2(30.81,3.76) v2(31.17,18.8) v2(31.37,11.96) v2(31.6,1.3) v2(31.88,6.76) v2(31.95,13.59) v2(32.61,8.33) v2(32.66,2.62) v2(32.79,28.8) v2(32.87,26.06) v2(32.89,21.29) v2(33.15,18.77) v2(33.12,12.4) v2(33.25,13.89) v2(33.32,24.21) v2(33.66,9.68) v2(34.04,3.78) v2(34.11,6.81) v2(34.37,22.78) v2(34.39,0.79) v2(34.47,25.35) v2(34.77,31.11) v2(34.92,28.17) v2(35.1,29.21) v2(35.28,8.08) v2(35.46,13.89) v2(36.02,12.06) v2(36.35,16.89) v2(36.58,10.16) v2(36.83,29.21) v2(36.96,6.43) v2(37.21,30.07) v2(37.24,0.74) v2(37.29,12.7) v2(37.77,13.97) v2(37.82,11.46) v2(38.1,10.16) v2(38.1,9.14) v2(38.2,31.09) v2(38.2,16.89) v2(38.15,7.57) v2(40.11,0.79) v2(40.64,10.16) v2(40.64,9.14) v2(40.69,16.89) v2(40.69,14.02) v2(40.74,11.48) v2(40.67,7.62) v2(40.84,29.31) v2(41.96,18.62) v2(42.09,26.26) v2(42.11,20.83) v2(42.24,13.46) v2(42.42,23.52) v2(42.47,31.06) v2(42.77,4.98) v2(42.93,9.65) v2(43.15,7.59) v2(43.64,2.24) v2(43.71,12.93) v2(43.84,18.9) v2(43.84,16.99) v2(43.94,21.21) v2(43.97,27.48) v2(44.5,24.59) v2(44.45,4.98) v2(45.21,9.91) v2(45.36,18.64) v2(45.39,17.14) v2(45.64,6.48) v2(45.67,22.4) v2(45.72,20.07) v2(45.72,13.03) v2(46.51,30.15) v2(46.71,2.34) v2(49.73,31.14) v2(51.05,2.29) v2(51.89,27.33) v2(52.22,25.93) v2(53.16,31.19) v2(53.59,21.08) v2(54.1,2.29) v2(54.18,7.92) v2(54.2,6.35) v2(54.86,26.67) v2(55.32,14.02) v2(55.42,12.75) v2(55.47,8.81) v2(55.83,11.46) v2(56.03,10.24) v2(56.13,28.45) v2(56.13,26.67) v2(57.91,30.48) v2(57.91,6.35) v2(58.93,9.96) v2(58.95,23.04) v2(59.18,7.11) v2(59.94,16) v2(60.45,30.48) v2(60.71,6.35) v2(60.96,10.16) v2(61.98,7.37) v2(62.23,27.69) v2(62.48,30.99) v2(63.25,10.41) v2(63.25,2.54) v2(63.5,6.35) v2(64.52,30.99) v2(64.52,27.18) v2(64.77,7.37) v2(64.9,20.93) v2(65.43,16.1) v2(65.53,25.91) v2(66.04,29.46) v2(66.04,6.35) v2(66.29,2.54) v2(66.8,24.89) v2(67.06,30.99) v2(67.06,28.45) v2(67.13,10.39) v2(67.08,9.35) v2(67.18,15.72) v2(67.18,11.35) v2(67.82,8.38) v2(68.07,29.46) v2(68.07,27.43) v2(68.33,6.6) v2(68.43,12.73) v2(68.48,11.58) v2(68.58,9.91) v2(69.09,30.99) v2(69.09,28.45) v2(69.27,26.39) v2(69.8,21.44) v2(69.77,13.59) v2(69.85,10.92) v2(69.9,23.8) v2(69.88,22.53) v2(70.1,29.46) v2(70.1,27.43) v2(70.05,25.15) v2(70.13,15.98) v2(70.1,8.38) v2(70.15,15.24) v2(70.38,19.99) v2(70.36,19.23) v2(70.61,12.7) v2(70.61,9.65) v2(70.74,21.79) v2(70.84,23.16) v2(70.92,26.59) v2(70.94,20.78) v2(70.97,24.54) v2(71.04,14.76) v2(71.12,30.99) v2(71.12,28.45) v2(71.32,25.53) v2(71.37,6.6) v2(71.63,23.8) v2(71.55,19.96) v2(71.63,13.72) v2(71.63,11.18) v2(71.63,8.13) v2(71.65,21.26) v2(71.75,22.58) v2(71.98,15.37) v2(72.14,29.46) v2(72.14,27.43) v2(72.16,24.49) v2(72.24,19.3) v2(72.44,23.29) v2(72.39,21.92) v2(72.44,20.7) v2(72.44,19.91) v2(72.52,25.43) v2(72.59,26.57) v2(72.57,14.61) v2(72.64,12.7) v2(72.9,9.91) v2(73.15,28.45) v2(73.2,15.29) v2(73.41,0.76) v2(73.58,26.11) v2(73.58,25.07) v2(73.66,13.72) v2(73.66,11.43) v2(74.04,14.66) v2(74.14,3.73) v2(74.17,29.46) v2(74.42,21.97) v2(74.45,6.32) v2(74.6,15.39) v2(74.68,30.99) v2(74.68,12.7) v2(74.75,16.48) v2(74.93,10.41) v2(75.18,2.03) v2(75.46,7.09) v2(75.49,3.73) v2(75.59,17.32) v2(75.69,28.45) v2(75.72,26.14) v2(75.69,18.44) v2(75.72,14.99) v2(75.69,13.72) v2(75.69,11.18) v2(75.84,16.23) v2(76.35,29.16) v2(76.56,31.04) v2(78.36,31.01) v2(78.61,26.72) v2(78.56,23.39) v2(78.59,16.51) v2(78.61,0.58) v2(78.66,14.83) v2(79.04,13.18) v2(79.5,11.18) v2(79.71,15.52) v2(80.19,31.01) v2(80.49,14.78) v2(80.64,13.18) v2(81.08,3.73) v2(81.48,29.26) v2(81.61,30.23) v2(82.35,30.96) v2(82.3,23.5) v2(82.55,29.29) v2(82.55,11.18) v2(82.93,22.91) v2(83.01,30.23) v2(83.03,15.65) v2(83.01,13.18) v2(83.06,14.43) v2(83.64,0.51) v2(83.85,29.08) v2(83.82,28.24) v2(83.97,27.33) v2(84.12,14.91) v2(84.33,31.01) v2(84.48,25.55) v2(84.58,11.43) v2(84.68,28.83) v2(84.68,27.91) v2(84.68,15.8) v2(84.96,13.18) v2(85.24,25.27) v2(85.19,22.2) v2(85.27,27.36) v2(85.52,29.24) v2(85.55,16.61) v2(85.78,28.14) v2(85.8,17.73) v2(85.8,14.83) v2(86.13,30.99) v2(86.11,11.68) v2(86.21,27.33) v2(86.64,28.63) v2(86.59,15.85) v2(86.59,13.16) v2(86.79,20.8) v2(86.79,19.51) v2(87,18.47) v2(87.1,27.71) v2(87.07,26.82) v2(87.4,17.09) v2(87.5,14.81) v2(87.6,30.25) v2(87.71,28.98) v2(88.06,20.19) v2(88.06,13.18) v2(88.16,26.82) v2(88.29,30.96) v2(88.27,16.21) v2(88.32,14) v2(88.44,29.57) v2(88.62,27.99) v2(88.65,26.04) v2(88.62,17.88) v2(88.72,0.53) v2(88.9,14.86) v2(89,30.28) v2(89,21.39) v2(88.98,18.97) v2(89.23,25.22) v2(89.36,26.85) v2(89.43,13.18) v2(89.53,22.17) v2(89.59,28.93) v2(89.59,16.66) v2(89.84,26.09) v2(89.81,20.14) v2(90.04,17.81) v2(90.22,25.12) v2(90.17,14.83) v2(90.27,30.99) v2(90.3,27.71) v2(90.35,15.9) v2(90.42,12.19) v2(90.47,26.64) v2(90.5,21.36) v2(90.81,18.95) v2(90.86,29.31) v2(91.24,26.09) v2(91.24,24.97) v2(91.19,20.17) v2(91.34,16.76) v2(91.26,13.11) v2(91.44,10.16) v2(91.49,17.98) v2(91.69,21.36) v2(91.72,14.91) v2(91.72,5.28) v2(91.8,31.01) v2(92.15,22.33) v2(92.3,29.21) v2(92.28,20.14) v2(92.53,17.55) v2(92.46,12.19) v2(92.46,8.13) v2(92.46,4.06) v2(92.46,1.02) v2(92.61,23.16) v2(92.56,19) v2(92.56,15.98) v2(92.71,21.39) v2(93.01,13.13) v2(93.14,30.99) v2(93.45,19.74) v2(93.52,18.54) v2(93.47,10.16) v2(93.47,6.1) v2(93.47,2.03) v2(94.34,29.84) v2(94.36,27.76) v2(94.49,12.19) v2(94.49,8.13) v2(94.49,4.06) v2(94.59,21.54) v2(94.6,19.54) v2(94.62,13.25) v2(94.74,30.73) v2(94.74,28.78) v2(94.72,17.42) v2(94.72,15.29) v2(94.95,27) v2(95.17,22.58) v2(95.28,20.52) v2(95.4,18.67) v2(95.48,29.87) v2(95.5,27.79) v2(95.5,16.38) v2(95.5,10.16) v2(95.5,6.1) v2(95.63,14.1) v2(95.91,30.78) v2(95.89,21.62) v2(95.99,28.73) v2(96.55,29.9) v2(96.47,22.58) v2(96.52,12.19) v2(96.52,8.13) v2(96.67,20.57) v2(96.7,15.19) v2(97.03,30.81) v2(97.08,19.35) v2(97.05,17.96) v2(97.08,16.59) v2(97.08,13.94) v2(97.23,21.56) v2(97.46,28.73) v2(97.56,29.74) v2(97.59,22.58) v2(97.61,12.8) v2(97.61,11.51) v2(97.61,10.21) v2(97.61,9.02) v2(97.64,7.67) v2(97.61,6.38) v2(97.61,5.23) v2(97.61,3.89) v2(97.71,23.75) v2(97.82,27.94) v2(97.89,20.65) v2(98.6,31.19) v2(98.6,30.18) v2(98.6,29.21) v2(98.6,28.22) v2(98.6,24.03) v2(98.6,22.58) v2(98.6,21.29) v2(98.6,19.99) v2(98.6,18.69) v2(98.6,17.4) v2(98.6,16.1) v2(98.6,14.81) v2(98.6,13.51) v2(98.6,12.22) v2(98.6,10.92) v2(98.6,9.63) v2(98.6,8.33) v2(98.6,7.04) v2(98.6,5.74) v2(98.6,4.45) v2(98.6,3.15) v2(98.6,1.85) v2(98.6,0.56) v5(61.47,19.53) v5(61.47,18.52) v5(61.47,17.5) v5(62.48,19.53) v5(62.5,18.52) v5(62.48,17.5) v5(63.5,19.53) v5(63.5,18.52) v5(63.5,17.5) v5(79.76,25.81) v5(79.76,24.38) v5(80.47,25.1) v5(81.18,25.81) v5(81.18,24.38) v7(43.92,28.91)
VDD_CC112X: length 139.8
  TOP w0.203: C9.1 65.1,15.09 v2(65.13,15.11) 64.02,15.11 63.75,15.39 U1.15 ; U1.13 62.75,14.13 C8.1 ; C8.1 62.36,14.07 62,13.72 v2(62,11.91) ; C8.1 62.69,14.07 ; U1.12 62.25,14.78 61.26,13.8 C4.1
  TOP w0.254: U1.5 57.51,18.27 C5.1 57.33,17.91 56.57,17.14 v2(56.57,16.94) ; v2(60.38,12.83) 60.91,13.36 C4.1
  TOP w0.305: 58.95,20.47 59.28,20.47 59.49,20.27 U1.1 ; 58.95,20.47 C7.1 ; 58.95,20.47 v2(58.95,20.93) ; C11.1 66.22,10.95 C12.1 66.29,11.02 R3.1 67.58,12.29 C10.2 ; 62.59,23.9 62.51,23.83 C17.1 61.82,23.47 62.75,22.55 U1.28 ; 62.59,23.9 62.59,25.17 v2(63.49,26.07) ; 62.59,23.9 62.59,23.52 62.94,23.16 C19.1 63.4,22.17 63.25,22.02 63.25,21.7 63.25,21.7 U1.27 ; U1.22 66.11,19.27 66.88,20.04 67.74,20.04 C18.1 68.15,21.05 v2(68.51,21.41) ; U1.25 64.25,21.27 65.81,22.84 C15.1 v2(66.65,23.16) ; R5.2 v2(55.07,29.46)
  TOP w0.508: C11.1 v4(66.22,8.48)
  TOP w0.762: L1.2 C2.1 C3.1
  TOP w1.016: v3(56.34,7.7) 56.39,7.65 v3(56.39,6.55) C3.1
  LAYER3 w0.203: 57.16,8.52 59.91,8.52 59.99,8.44 62,8.44 62,8.43
  LAYER3 w0.508: v2(56.57,16.94) 56.12,16.49 55.28,15.66 ; 68.51,23.04 68.39,23.16 v2(66.65,23.16) ; 54.1,22.76 57.12,22.76 v2(58.95,20.93) ; v2(63.49,26.07) 63.49,28.99 63.42,29.06 ; 55.12,30.63 55.07,30.58 v2(55.07,29.46) ; v2(60.38,12.83) 60.35,12.83 59.99,12.47 59.99,8.44 ; 57.16,13.84 58.43,15.11 v2(65.13,15.11) ; v2(62,11.91) 62,8.43
  LAYER3 w1.016: v3(56.39,6.55) 56.37,6.57 56.37,8.43 62,8.43 62.05,8.48 v4(66.22,8.48) ; v3(56.34,7.7) 56.34,7.72 ; v2(68.51,21.41) 68.51,24.92 64.37,29.06 57.23,29.06 55.65,30.63 54.38,30.63 53.31,29.57 53.31,26.59 54.08,25.83 54.08,22.78 54.94,21.92 54.94,21.36 54.98,21.32 54.98,19.88 54.61,19.51 54.61,16.33 56.39,14.55 56.44,14.55 57.16,13.84 57.16,8.52
VDD_CC1190: length 43.7
  TOP w0.508: L6.1 82.69,20.92 R12.2 81.61,20.89 C30.1 81.61,19.53 v4(80.98,18.9) ; L7.1 84.25,22.53 C31.1 84.25,20.19 C32.1 C33.1 ; v3(73.25,7.82) 73.28,7.85 P6.2 ; C33.1 84.3,18.9 ; C33.1 v4(84.23,18.14) ; L5.2 v4(79.22,18.82)
  TOP w0.762: L4.2 73.2,5.36 C28.1
  TOP w1.016: C28.1 v3(73.23,6.71) 73.23,7.8 v3(73.25,7.82)
  LAYER3 w1.016: 80.98,16.66 81.81,16.66 ; 80.98,16.66 80.24,16.66 79.22,17.67 v4(79.22,18.82) ; 80.98,16.66 v4(80.98,18.9) ; 81.81,16.66 81.81,11.99 78.89,9.07 74.24,9.07 73.23,8.05 v3(73.23,6.71) ; 81.81,16.66 83.79,16.66 84.23,17.09 v4(84.23,17.3) v4(84.23,18.14)
VDD_CC2511: length 50.4
  TOP w0.254: U4.28 23.6,11.47 22.81,10.69 22.81,10.11 ; v2(26.42,19.71) 26.62,19.71 26.78,19.55 C41.2 27.25,18.97 26.83,18.54 26.81,18.54 26.6,18.33 U4.12 ; 22.81,10.11 C48.2 ; 22.81,10.11 24.1,11.4 U4.29 ; U4.2 30.03,13.2 v2(30.53,12.7) ; v2(21.03,11.66) 21.14,11.77 21.14,12.13 20.85,12.42 C47.1 21.53,13.2 U4.26 ; U4.19 21.96,16.7 v2(21.52,17.15) 21.13,17.53 C43.1 ; U4.22 21.13,15.2 C45.2 21.46,14.34 v2(21.46,14.33) 21.46,14 21.21,13.74 C46.2 20.93,13.7 U4.25
  TOP w0.305: C48.2 v2(21.89,10.07)
  TOP w0.762: L12.2 C42.1 21.46,9.64 v2(21.89,10.07)
  LAYER3 w0.254: v2(30.53,12.7) 30.02,13.21 29.39,13.21 29.26,13.34 ; 22.29,11.66 v2(21.03,11.66) ; 28.18,17.79 27.94,17.55 ; v2(21.46,14.33) 21.93,14.33 22.33,13.93 ; v2(21.52,17.15) 21.88,16.79 22.3,16.79 ; v2(26.42,19.71) 25.86,19.71 24.87,18.72 24.87,17.78
  LAYER3 w0.762: v2(21.89,10.07) 21.89,11.26 22.33,11.7 22.33,14.02 22.3,14.05 22.3,16.79 23.29,17.78 27.71,17.78 29.26,16.23 29.26,13.34
CC112X_RF: length 5.6
  TOP w0.254: 72.38,17.26 72.39,17.27
  TOP w0.305: 72.39,17.27 72.67,17.27 ; FL1.2 72.38,17.26
  TOP w0.711: FL2.5 74.42,18.99 74.43,18.97 74.43,18.03 73.67,17.27 72.67,17.27
COM_5V: length 7.7
  TOP w0.508: 36.01,27.38 36.01,28.29 C56.2
  TOP w1.016: 36.01,27.38 U5.3 34.95,26.42 34.14,27.23 C57.1 P7.2
DBG_DC: length 34.1
  TOP w0.254: P1.3 14.35,1.93 v2(14.86,1.42) ; v2(24.33,20.6) 24.33,19 24.6,18.73 U4.16
  LAYER3 w0.254: v2(15.21,11) 15.21,18.19 17.17,20.14 19.86,20.14 20.14,20.42 21.89,20.42 22.5,21.03 22.5,21.39 22.89,21.77 23.98,21.77 24.33,21.41 v2(24.33,20.6)
  BOTTOM w0.254: v2(14.86,1.42) 14.86,10.64 v2(15.21,11)
DBG_DD: length 28.9
  TOP w0.254: U4.15 25.1,18.42 25.28,18.6 v2(25.28,20.14) ; P1.4 14.35,10.57 v2(13.97,10.95)
  LAYER3 w0.254: v2(13.97,10.95) 13.97,18.85 16.21,21.08 21.29,21.08 22.58,22.38 24.61,22.38 25.28,21.71 v2(25.28,20.14)
DCPL_XOSC: length 8.6
  TOP w0.305: R28.2 59.62,27.69 59.8,27.51 59.8,26.17 60.18,25.78 C21.1 61.01,25.55 61.01,23.47 62.25,22.24 U1.29
HGM: length 25.5
  TOP w0.254: U2.6 80.8,28.7 v2(80.54,28.96) ; R23.1 v2(76.94,10.62)
  BOTTOM w0.254: v2(80.54,28.96) 79.93,29.57 77.75,29.57 76.63,28.45 76.63,11 76.94,10.69 v2(76.94,10.62)
LNA_EN: length 27.2
  TOP w0.254: v2(77.62,11.86) 82.98,11.86 83.34,11.51 R24.1 ; U2.7 v2(80.15,28.06)
  BOTTOM w0.254: v2(80.15,28.06) 79.32,28.88 78.16,28.88 77.86,28.59 77.86,28.54 77.24,27.91 77.24,12.24 v2(77.62,11.86)
LNA_EN_LP: length 97.7
  TOP w0.254: v2(36.14,3.17) 41.94,3.17 43.05,4.29 44.88,4.29 v2(45.31,4.72)
  TOP w0.305: P6.6 v2(82.35,10.24)
  LAYER3 w0.254: v2(45.31,4.72) 46.25,5.66 81.99,5.66 82.35,6.02 v2(82.35,10.24) ; v2(36.14,3.17) v2(11.94,3.17)
  BOTTOM w0.254: 4.45,17.14 5.74,15.85 9.88,15.85 11.33,14.4 11.33,3.78 v2(11.94,3.17)
LP_5V: length 29.6
  TOP w1.016: P7.3 27.9,29.56 v4(30.45,29.56) v4(31.62,29.56)
  LAYER3 w1.016: v4(31.62,29.56) v4(30.45,29.56) 9.24,29.56 P2.2
Net_2:
  vias: v1(108.31,23.05) v1(113.31,25.05)
Net_3:
  vias: v1(108.31,21.05) v1(113.31,23.05)
Net_4:
  vias: v1(108.31,19.05) v1(113.31,21.05)
Net_5:
  vias: v1(108.31,17.05) v1(113.31,19.05)
Net_6:
  vias: v1(108.31,15.05) v1(113.31,17.05)
Net_7:
  vias: v1(108.31,13.05) v1(113.31,15.05)
Net_8:
  vias: v1(108.31,11.05) v1(113.31,13.05)
Net_9:
  vias: v1(108.31,9.05) v1(113.31,11.05)
Net_10:
  vias: v1(108.31,7.05) v1(113.31,9.05) v1(113.31,7.05)
Net_11:
  vias: v1(108.31,25.05) v1(113.31,27.05)
PA_EN: length 28.6
  TOP w0.254: v2(79.1,28.1) 79.5,27.71 U2.8 ; v2(78.41,12.55) 87.89,12.55 88.72,11.71 R25.1
  BOTTOM w0.254: v2(79.1,28.1) 78.49,28.1 77.93,27.53 77.93,13.03 v2(78.41,12.55)
PA_EN_LP: length 97.3
  TOP w0.254: v2(45.77,3.07) 43.26,3.07 42.21,2.03 v2(35.59,2.03)
  TOP w0.305: P6.10 v2(87.43,10.13)
  LAYER3 w0.254: v2(35.59,2.03) 10.03,2.03 9.4,2.67 9.4,7.34 8.48,8.26 5.71,8.26 4.45,9.53 ; v2(45.77,3.07) 54.99,3.07 55.52,3.61 72.52,3.61 73.03,3.1 84.53,3.1 87.43,5.99 v2(87.43,10.13)
RF_GPIO0: length 117.5
  TOP w0.203: v2(54.89,10.79) 57.51,10.79 59.05,12.34 59.05,13.72 59.79,14.45 60.58,14.45 61.25,15.12 U1.10
  TOP w0.254: v2(36.22,10.87) v2(43.03,10.87) ; v2(25.76,10.87) 25.76,11.12 25.72,11.16 25.72,11.21 25.6,11.33 U4.32
  TOP w0.305: P6.12 v2(89.97,10.21)
  LAYER3 w0.203: 55.09,4.37 55.07,4.39 v2(55.04,4.39) ; v2(54.89,10.79) 52.76,10.79 v2(52.43,10.46)
  LAYER3 w0.254: 55.09,4.37 84.66,4.37 86.11,5.82 86.11,10.54 87.12,11.56 88.62,11.56 v2(89.97,10.21)
  BOTTOM w0.203: v2(54.89,10.79) 54.89,4.55 v2(55.04,4.39) ; v2(52.43,10.46) 52.43,21.03 53.24,21.84 53.24,23.47 51.99,24.71 50.22,24.71 P3.4
  BOTTOM w0.254: P3.4 48.87,23.47 43.97,23.47 43.03,22.53 v2(43.03,10.87) ; v2(25.76,10.87) v2(36.22,10.87)
RF_GPIO2: length 88.5
  TOP w0.203: v2(52.96,18.77) U1.4
  TOP w0.254: P3.18 48.9,8.26 46.25,8.26 44.78,6.78 37.8,6.78 30.88,13.7 U4.3
  TOP w0.305: P6.8 v2(84.89,10.26)
  LAYER3 w0.203: v2(84.89,10.26) 84.89,6.38 83.59,5.08 53.29,5.08 v2(52.98,4.78) ; P3.18 v2(52.17,6.99)
  BOTTOM w0.203: 53.01,7.01 53.01,10.66 52.96,10.71 v2(52.96,18.77) ; 53.01,7.01 52.99,6.99 v2(52.17,6.99) ; 53.01,7.01 53.01,6.55 52.98,6.52 v2(52.98,4.78)
RF_GPIO3: length 51.5
  TOP w0.203: v2(53.49,19.51) 54.13,19.51 54.37,19.27 U1.3
  TOP w0.254: U4.1 29.31,12.7 36.35,5.66 48.97,5.66 49.12,5.51 49.12,5.49 P3.20
  LAYER3 w0.203: P3.20 51.22,4.45 51.52,4.14 v2(54.15,4.14)
  BOTTOM w0.203: v2(54.15,4.14) 53.49,4.8 v2(53.49,19.51)
RF_RESET_N: length 48.6
  TOP w0.203: U1.2 55.01,19.77 54.53,20.24 v2(53.87,20.24)
  TOP w0.254: v2(45.01,8.36) 37.44,8.36 35.28,10.52 35.28,12.75 32.83,15.2 U4.6
  LAYER3 w0.203: P3.16 50.88,8.81 v2(54.15,8.81)
  LAYER3 w0.254: P3.16 48.9,8.26 45.11,8.26 v2(45.01,8.36)
  BOTTOM w0.203: v2(54.15,8.81) 54.15,20.07 53.98,20.24 v2(53.87,20.24)
RF_SPI_CS_N: length 57.6
  TOP w0.203: v2(55.45,9.65) 57.76,9.65 59.56,11.46 59.56,13.21 60.38,14.02 60.83,14.02 61.75,14.94 U1.11
  TOP w0.254: v2(43.9,13.83) 43.1,14.63 34.92,14.63 33.86,15.7 U4.7
  LAYER3 w0.203: v2(55.45,9.65) v2(51.92,9.65)
  BOTTOM w0.203: P3.6 51.22,22.23 51.92,21.53 v2(51.92,9.65)
  BOTTOM w0.254: v2(43.9,13.83) 44.63,14.55 44.63,20.7 44.88,20.95 48.9,20.95 P3.6
RF_SPI_MISO(GPIO1): length 46.3
  TOP w0.203: U1.9 60.75,15.33 60.3,14.88 59.44,14.88 58.34,13.79 58.34,12.98 57.43,12.06 v2(54.79,12.06)
  TOP w0.254: v2(45.41,12.06) v2(41.53,12.06) ; U4.13 26.1,18.33 26.09,18.34 v2(26.09,18.95) ; v2(30.05,18.95) 30.99,18.01 35.59,18.01 36.04,17.55 v2(41.5,17.55)
  LAYER3 w0.203: v2(54.79,12.06) P3.14
  LAYER3 w0.254: v2(45.41,12.06) 45.41,11.05 45.67,10.79 48.9,10.79 P3.14
  BOTTOM w0.254: v2(26.09,18.95) v2(30.05,18.95) ; v2(41.5,17.55) 41.5,16.94 41.53,16.92 v2(41.53,12.06)
RF_SPI_MOSI: length 34.6
  TOP w0.203: U1.7 59.08,17.27 58.62,16.81 58.62,15.67 57.63,14.68 v2(54.76,14.68)
  TOP w0.254: U4.9 29.23,16.7 29.72,17.2 35.08,17.2 36.04,16.23 45.23,16.23 v2(45.59,15.88)
  LAYER3 w0.203: P3.12 50.24,14.68 v2(54.76,14.68)
  LAYER3 w0.254: P3.12 48.9,15.88 v2(45.59,15.88)
RF_SPI_SCLK: length 89.7
  TOP w0.203: v2(54.76,13.39) 57.15,13.39 59.18,15.42 59.18,16.59 59.36,16.77 U1.8
  TOP w0.254: U4.8 29.69,16.2 29.95,16.46 34.16,16.46 35.08,15.54 44.2,15.54 v2(45.62,14.12) ; v2(41.55,4.37) v2(37.01,4.37)
  LAYER3 w0.203: 46.35,13.39 v2(54.76,13.39)
  LAYER3 w0.254: v2(10.46,4.37) v2(37.01,4.37) ; v2(45.62,14.12) 46.35,13.39
  BOTTOM w0.254: 4.45,12.06 5.74,10.77 9.19,10.77 10.11,9.86 10.11,4.73 v2(10.46,4.37) ; v2(41.55,4.37) 41.55,4.88 44.37,7.7 44.37,12.88 v2(45.62,14.12)
USB_5V: length 33
  TOP w0.254: v2(29.69,9.49) 28.87,10.31 R21.2
  TOP w0.305: v2(32.82,22.71) 30.84,24.69 P7.1
  TOP w0.508: 20.71,26.18 20.24,26.65 J4.1
  TOP w1.016: P7.1 22.2,24.69 20.71,26.18
  LAYER3 w0.305: v2(29.69,9.49) 30.23,9.49 30.24,9.47 32.23,9.47 34.09,11.33 34.09,21.44 v2(32.82,22.71)
USB_ENABLE: length 4.1
  TOP w0.254: R22.2 R21.1 27.97,10.51 27.58,10.89 26.53,10.89 26.1,11.32 U4.33
USB_PULLUP: length 2
  TOP w0.254: U4.4 29.49,14.2 29.72,14.43 29.76,14.43 29.79,14.45 R16.2
USB_RESET: length 19.6
  TOP w0.254: 25.52,2.22 SW1.1 ; SW1.1 25.65,3.14 26.52,4 26.52,7.25 25.9,7.87 R26.1 25.32,8.45 25.3,8.48 R17.2 25.32,9.13 ; SW1.1 25,2.08 24.99,2.09 R27.2 23.35,2.09 23.34,2.08 22.43,2.08 21.72,1.37 17.2,1.37 16.89,1.68 P1.7
N333157: length 2.5
  TOP w0.305: L2.1 C13.1 66.11,16.77 U1.17
N333170: length 2.6
  TOP w0.305: C10.1 67.58,13.19 R3.2 L2.2
N333547: length 2.5
  TOP w0.508: C13.2 R7.2 68.1,16.29 R8.2
N333561: length 2.5
  TOP w0.305: R7.1 69.47,16.76 FL1.9
  TOP w0.508: R7.1 R9.2
N333614: length 5.5
  TOP w0.254: FL1.8 70.48,17.27 U1.18
N333626: length 5.5
  TOP w0.254: U1.20 70.48,18.27 FL1.6
N333651: length 5.5
  TOP w0.254: U1.19 70.48,17.77 FL1.7
N334768: length 2.3
  TOP w0.203: U1.14 63.25,15.32 63.94,14.63 63.94,14.1 R1.1
N334780: length 2.4
  TOP w0.305: C16.2 66.4,21.89 65.53,21.02 65.53,20.57 65.23,20.27 U1.24
N334837: length 3.8
  TOP w0.305: U1.23 65.72,19.77 66.62,20.68 67.01,20.68 67.31,20.98 C16.1
N335035: length 9.8
  TOP w0.305: C25.2 54.37,25.39 U3.4 53.95,25.65 53.95,25.65 53.95,26.31 53.64,26.62 CR2.1 53.19,27.4 53.29,27.5 53.29,27.51 53.47,27.69 R5.1 R28.1
N335193: length 7
  TOP w0.305: U1.30 61.75,21.95 60.38,23.32 60.38,24.55 60.11,24.82 59.36,24.82 Y1.1 59.36,26.04 59.05,26.34 C22.2
N335253: length 6.8
  TOP w0.305: 56.54,24.09 C23.2 56.79,23.84 Y1.3 57.91,23.14 58.85,22.2 60.74,22.2 61.25,21.7 U1.31
N337409: length 1.4
  TOP w0.254: 71.94,17.76 72.18,17.76 72.72,18.3 R10.2
  TOP w0.305: 71.94,17.76 FL1.3
N339345: length 2.6
  TOP w0.305: C20.1 64.67,22.66 63.75,21.73 U1.26
N339363: length 2.9
  TOP w0.305: U1.21 66.5,18.77 66.93,19.2 C14.1
N339381: length 2.9
  TOP w0.203: C6.1 57.81,16.99 57.78,17.02 57.78,17.37 58.18,17.77 U1.6
N340434: length 5.9
  TOP w0.254: 58.02,21.51 58,21.54 R4.2
  TOP w0.305: C24.1 57.33,22.81 58.02,22.11 58.02,21.51 ; R4.2 58.02,21.62 60.4,21.62 60.75,21.27 U1.32
N340490: length 1.5
  TOP w0.305: C24.2 55.33,22.87 U3.3
N342853: length 4.3
  TOP w0.305: U2.10 78.55,25.34 78.09,25.34 ; 78.07,24.83 78.55,24.83 U2.11
  TOP w0.508: 78.09,25.34 77.83,25.07 ; 77.83,25.07 75.66,25.07 75.58,24.99 L3.2 ; 77.83,25.07 78.07,24.83
N342874: length 2.9
  TOP w0.508: FL2.2 74.42,24.28 74.42,24.29 L3.1 74.42,26.18 C26.2
N343088: length 1.5
  TOP w0.305: U2.14 80.15,22.1 R11.2
N343666: length 1.7
  TOP w0.305: R12.1 81.58,21.82 81.07,22.34 81.06,22.34 80.8,22.61 U2.15
N343673: length 2
  TOP w0.305: L6.2 82.73,22.1 81.6,23.23 U2.16
N343813: length 2.7
  TOP w0.305: L5.1 79.27,20.68 C29.1 79.27,22.45 79.5,22.68 U2.13
N344199: length 4.4
  TOP w0.254: 83.63,24.75 L7.2
  TOP w0.305: U2.2 83.63,24.75
  TOP w0.508: L13.1 C35.1 84.1,24.28 L7.2
N344697: length 4.1
  TOP w0.305: C34.2 82.92,27.98 83.29,27.61 83.29,26.65 83.44,26.49 ; 83.44,26.49 83.47,26.47 C36.1 ; 83.44,26.49 83.08,26.49 82.65,26.05 U2.4
N344701: length 1.8
  TOP w0.305: U2.5 81.45,27.88 81.49,27.93 81.49,27.93 82.01,28.45 C34.1
N344947: length 4.8
  TOP w0.508: C60.1 88.62,23.16 L9.1 87.46,24.28 C37.2 86.25,24.27 C35.2 86.24,25.44 L8.1
N345002: length 3.8
  TOP w0.508: C60.2 89.6,23.09 L9.2 89.82,24.06 C38.2 90.84,24.05 L10.1
N345235: length 3.9
  TOP w0.203: 92.65,24.95 L10.2
  TOP w0.305: 94.27,24.95 94.29,24.97 J3.1
  TOP w0.508: L10.2 C39.2
  TOP w0.711: 94.27,24.95 92.65,24.95
N348306: length 2.8
  TOP w0.203: 97.79,26.82 97.76,26.85 L11.1
  TOP w0.305: 99.09,27.05 A1.1
  TOP w0.508: 97.79,26.82 C40.2 ; L11.1 99.09,27.05
N349314: length 2
  TOP w0.254: U4.30 24.6,11.21 24.03,10.64 C44.1 24.05,10.08
N350057: length 17.8
  TOP w0.254: R14.2 C49.1 18.48,22.77 18.48,22.21 19.38,21.31 21.89,21.31 22.75,22.16 28,22.16 28.75,21.41 28.75,18.19 28.17,17.6 U4.10
N350061: length 27
  TOP w0.254: v2(17.45,25.04) 18.39,25.04 R14.1 18.49,25.55 18.94,26.01 J4.3 ; v2(32.08,14.45) R16.1
  LAYER3 w0.254: v2(32.08,14.45) 32.08,20.75 28.92,23.91 23.71,23.91 22.58,25.04 v2(17.45,25.04)
N350083: length 15.1
  TOP w0.254: v2(20.55,23.9) 19.85,23.9 R15.2 C50.1 ; v2(28.09,20.07) 28.09,19.08 27.1,18.08 U4.11
  LAYER3 w0.254: v2(20.55,23.9) 20.8,23.65 22.3,23.65 22.99,22.96 25.5,22.96 26.49,21.97 27.84,21.97 28.09,21.72 v2(28.09,20.07)
N350090: length 2.3
  TOP w0.254: R15.1 19.59,25.06 J4.2
N350965: length 3.1
  TOP w0.254: U4.31 25.1,10.84 25.1,10.83 25.1,10.26 R17.1 C51.1
N351165: length 3.3
  TOP w0.254: U4.27 22.37,12.7 21.89,12.22 21.89,11.25 21.34,10.69 R18.2
N351342: length 7.1
  TOP w0.254: Y2.1 16.84,16.18 17.58,15.44 C52.1 18.36,14.94 19.13,15.7 U4.21
N351349: length 5
  TOP w0.254: Y2.3 18.36,17.5 C53.1 19.81,17.5 20.13,17.18 20.16,17.18 21.14,16.2 U4.20
N352690: length 11.9
  TOP w0.254: CR1.2 12.83,19.32 v2(17.59,19.32) ; v2(22.2,18.72) 22.2,18.52 22.56,18.16 23.39,18.16 23.6,17.96 U4.18
  LAYER3 w0.254: v2(22.2,18.72) 20.68,18.72 20.08,19.32 v2(17.59,19.32)
N352702: length 6.2
  TOP w0.254: CR1.1 12.75,12.77 12.78,12.75 R19.1
N352706: length 2.1
  TOP w0.254: U4.17 24.1,18.27 23.32,19.05 R20.1
N367241: length 10.5
  TOP w0.254: R25.2 88.72,2.9
  TOP w0.305: P6.9 P6.11
N367275: length 10.3
  TOP w0.254: R24.2 83.62,3 83.72,2.9
  TOP w0.305: P6.5 P6.7
N367294: length 10.3
  TOP w0.254: 78.61,2.9 78.61,10.55 78.62,10.56 R23.2
  TOP w0.305: P6.3 P6.1
N398938: length 1.2
  TOP w0.508: L8.2 84.98,26.46 C36.2
N399362: length 1.2
  TOP w0.508: L13.2 C59.1
N401261: length 1.1
  TOP w0.305: 97.05,24.97 J3.2
  TOP w0.711: C40.1 97.05,24.97

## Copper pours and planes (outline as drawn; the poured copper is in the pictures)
GND on TOP (solid shape): 78.13,26.09 76.33,26.09 76.33,29.92 78.13,29.92
GND on TOP (solid shape): 93.75,13.13 76.35,13.13 76.35,14.81 93.75,14.81
GND on TOP (solid shape): 94.23,29.51 76.12,29.51 76.12,31.19 94.23,31.19
GND on TOP (solid shape): 78,23.62 78,14.17 77.95,14.12 76.15,14.12 76.15,23.6 76.58,24.03 77.6,24.03
GND on TOP (solid shape): 94.23,29.87 94.23,26.21 94.21,26.19 92.99,26.19 92.99,26.52 92.71,26.8 92.71,29.9 94.21,29.9
GND on TOP (solid shape): 94.34,23.83 94.34,13.28 94.18,13.13 92.48,13.13 92.46,13.16 92.46,23.32 93.14,24 94.16,24
GND on TOP (solid shape): 85.6,25.7 85.6,24.99 85.5,24.89 84.86,24.89 84.51,25.25 82.32,25.25 82.32,25.6 83.13,25.6 83.39,25.86 85.45,25.86
GND on TOP: 75.41,20.27 75.41,17.53 74.32,16.43 72.31,16.43 72.03,16.71 72.03,16.74 71.04,16.74 70.89,16.59 70.89,16.21 70.84,16.15 69.88,16.15 69.72,16 69.72,14.1 76.15,14.1 76.96,14.91 76.96,20.24 76.94,20.27
GND on TOP, BOTTOM, LAYER2, LAYER3: 0.25,0.25 0.25,31.5 98.88,31.5 98.88,0.25
Net_2 on BOTTOM (solid shape): 112.96,25.41 113.66,25.41 113.66,24.7 112.65,23.68 112.49,23.58 112.3,23.54 109.5,23.54 108.66,22.7 107.96,22.7 107.96,23.41 108.94,24.39 109.11,24.5 109.3,24.54 112.09,24.54
Net_3 on BOTTOM (solid shape): 112.96,23.41 113.66,23.41 113.66,22.7 112.65,21.69 112.49,21.58 112.3,21.54 109.5,21.54 108.66,20.7 107.96,20.7 107.96,21.41 108.94,22.39 109.11,22.5 109.3,22.54 112.09,22.54
Net_4 on BOTTOM (solid shape): 112.96,21.41 113.66,21.41 113.66,20.7 112.65,19.68 112.49,19.58 112.3,19.54 109.5,19.54 108.66,18.7 107.96,18.7 107.96,19.41 108.94,20.39 109.11,20.5 109.3,20.54 112.09,20.54
